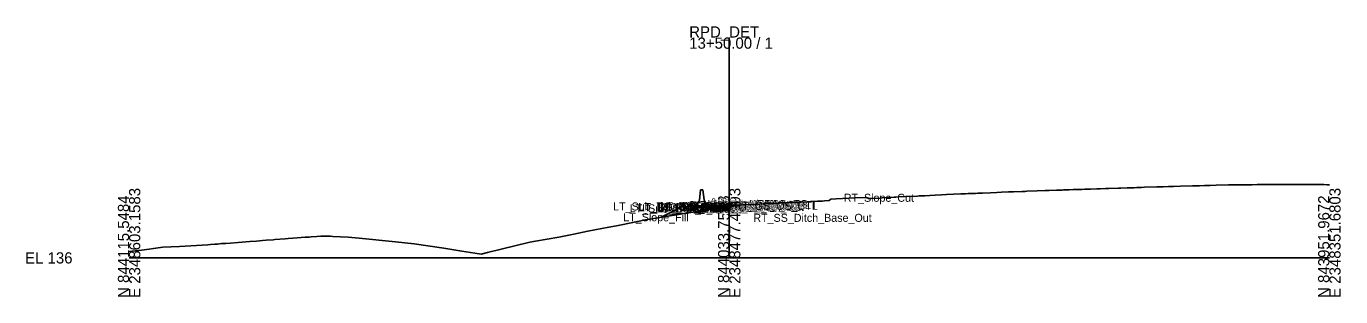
# Model space of a CAD drawing. Extents: x -26 to 2348503, y -10 to 844218.
# Drawn here: x -25.7 to 302.8, y 3490.3 to 3557.9 of the extents above; entities that cross this region are included whole.
import ezdxf

# ---------------------------------------------------------------- set-up
doc = ezdxf.new("R2010")
doc.units = 0
for name, color, linetype in [('Default', 7, 'Continuous'), ('Exist Cross Section Cell', 7, 'Continuous'), ('Exist XS Center Line Elevation Label', 7, 'Continuous'), ('Exist XS Ground Line', 7, 'Continuous'), ('Old_Level_1', 7, 'Continuous'), ('Prop CMT Pvmt Course 1', 7, 'Continuous'), ('Prop CMT Pvmt Course 1 Wedge', 7, 'Continuous'), ('Prop CMT Pvmt Course 2', 7, 'Continuous'), ('Prop CMT Pvmt Course 2 Wedge', 7, 'Continuous'), ('Prop CMT Pvmt Course 3', 7, 'Continuous'), ('Prop CMT Pvmt Course 3 Wedge', 7, 'Continuous'), ('Prop CMT Pvmt Surface', 7, 'Continuous'), ('Prop CMT Pvmt Surface Shoulder', 7, 'Continuous'), ('Prop CMT Pvmt Wedge Surface 1', 7, 'Continuous'), ('Prop CMT Pvmt Wedge Surface 2', 7, 'Continuous'), ('Prop CMT Pvmt Wedge Surface 3', 7, 'Continuous'), ('Prop CMT Shld Paved Course 1', 7, 'Continuous'), ('Prop CMT Shld Paved Course 2', 7, 'Continuous'), ('Prop CMT Shld Paved Course 3', 7, 'Continuous'), ('Prop CMT Slope Grass', 7, 'Continuous'), ('Prop CMT Subgrade Earthwork', 7, 'Continuous'), ('Prop XS Earthwork Shape', 7, 'Continuous'), ('Prop XS SE Text', 7, 'Continuous'), ('Typical Median Barrier CELL', 7, 'Continuous')]:
    doc.layers.add(name, color=color, linetype=linetype)

# ---------------------------------------------------------------- blocks, each defined once
blk = doc.blocks.new('TYPE T DOUBLE FACE BARRIER')
at = {"layer": 'Typical Median Barrier CELL'}
for p, q in [((-0.33, 3.83), (-0.6, 1.3)), ((0, 3.83), (-0.33, 3.83)), ((0, 3.83), (0.33, 3.83)), ((0.33, 3.83), (0.6, 1.3)), ((-0.75, 0.91), (-1.21, 0.25)), ((-1.21, -0.17), (-1.21, 0.25)), ((0, 0), (0, 0)), ((0.75, 0.91), (1.21, 0.25)), ((1.21, -0.17), (1.21, 0.25)), ((-1.21, -0.17), (1.21, -0.17))]:
    blk.add_line(p, q, dxfattribs=at)
for centre, start, end in [((-1.43, 1.38), 325.0039, 353.9447), ((1.43, 1.38), 186.0553, 214.9937)]:
    blk.add_arc(centre, 0.833, start, end, dxfattribs=at)

msp = doc.modelspace()

# ---------------------------------------------------------------- linework, layer by layer
at = {"layer": 'Exist Cross Section Cell'}
for p, q in [((150, 3500), (150, 3555.06)), ((0, 3500), (150, 3500)), ((150, 3500), (300, 3500))]:
    msp.add_line(p, q, dxfattribs=at)
at = {"layer": 'Exist XS Ground Line'}
msp.add_lwpolyline([(0, 3501.59), (3.14, 3501.96), (4.99, 3502.16), (6.14, 3502.32), (8.43, 3502.68), (12.64, 3502.87), (19.65, 3503.25), (20.33, 3503.31), (21.47, 3503.41), (21.78, 3503.43), (22.08, 3503.46), (23.09, 3503.56), (23.44, 3503.57), (24.16, 3503.61), (25.37, 3503.71), (27.26, 3503.86), (30.18, 3504.09), (31.84, 3504.22), (33.34, 3504.35), (34.29, 3504.44), (36.05, 3504.54), (36.4, 3504.57), (39.03, 3504.77), (39.79, 3504.84), (40.94, 3504.92), (42.05, 3505), (44, 3505.14), (44.97, 3505.21), (45.52, 3505.25), (46.95, 3505.35), (47.91, 3505.39), (48.81, 3505.41), (50.31, 3505.4), (50.91, 3505.37), (54.76, 3505.17), (57.47, 3504.96), (66.58, 3504.02), (71.26, 3503.52), (78.63, 3502.42), (83.21, 3501.71), (86.44, 3501.22), (88.04, 3500.96), (89.59, 3501.36), (100.17, 3503.96), (101.61, 3504.2), (107.4, 3505.19), (111.17, 3505.95), (114.63, 3506.66), (119.95, 3507.69), (121.85, 3508.05), (123.1, 3508.28), (129.08, 3509.54), (142.45, 3511.66), (145.9, 3512.25), (146.83, 3512.35), (150, 3512.78), (151.18, 3512.94), (152, 3513.06), (153.48, 3513.26), (155.66, 3513.37), (157.28, 3513.44), (158.7, 3513.5), (160.22, 3513.57), (160.9, 3513.6), (161.34, 3513.62), (163.68, 3513.74), (164.75, 3513.8), (167.33, 3513.91), (169.38, 3514.01), (169.94, 3514.04), (170.31, 3514.06), (172.05, 3514.15), (173.21, 3514.21), (173.83, 3514.25), (175.02, 3514.35), (175.41, 3514.68), (176.69, 3514.75), (181.47, 3514.99), (184.29, 3515.13), (184.8, 3514.8), (185.45, 3514.84), (187.69, 3514.94), (188.22, 3514.97), (189.83, 3515.07), (191.2, 3515.15), (191.64, 3515.18), (192.34, 3515.22), (194.18, 3515.31), (197.06, 3515.45), (197.44, 3515.48), (198.19, 3515.51), (198.86, 3515.53), (200.12, 3515.59), (201.5, 3515.66), (203.1, 3515.74), (204.29, 3515.81), (206.09, 3515.89), (207.9, 3515.97), (209.08, 3516.02), (209.71, 3516.06), (210.68, 3516.1), (211.55, 3516.13), (212.11, 3516.15), (213.34, 3516.19), (215.27, 3516.26), (216.93, 3516.34), (218.02, 3516.39), (219.81, 3516.47), (221.05, 3516.52), (223.24, 3516.59), (223.97, 3516.62), (224.39, 3516.64), (226.96, 3516.74), (229, 3516.81), (229.98, 3516.84), (231.84, 3516.91), (233.19, 3516.95), (233.56, 3516.97), (235.01, 3517.02), (235.95, 3517.05), (236.82, 3517.08), (238.17, 3517.13), (238.92, 3517.15), (240.32, 3517.2), (241.89, 3517.25), (242.22, 3517.26), (242.74, 3517.28), (244.03, 3517.31), (244.86, 3517.34), (247.27, 3517.42), (247.85, 3517.44), (249.45, 3517.47), (250.83, 3517.53), (251.23, 3517.54), (251.85, 3517.57), (253.04, 3517.62), (253.82, 3517.64), (256.84, 3517.73), (258.47, 3517.79), (259.79, 3517.83), (260.29, 3517.84), (261.06, 3517.86), (262.77, 3517.92), (265.76, 3518.01), (267.51, 3518.04), (268.76, 3518.09), (269.33, 3518.1), (270.21, 3518.12), (271.72, 3518.15), (274.8, 3518.22), (276.58, 3518.24), (277.72, 3518.26), (279.37, 3518.28), (280.67, 3518.29), (281.96, 3518.31), (283.96, 3518.34), (286.62, 3518.35), (288.55, 3518.35), (289.63, 3518.35), (291, 3518.33), (292.59, 3518.35), (293.11, 3518.35), (294.79, 3518.33), (295.58, 3518.33), (296.4, 3518.32), (297.72, 3518.31), (298.59, 3518.3), (299.48, 3518.28), (300, 3518.28)], dxfattribs=at)
at = {"layer": 'Prop CMT Pvmt Course 1'}
for p, q in [((150, 3513.15), (142, 3512.98)), ((142, 3512.98), (142, 3512.73)), ((142, 3512.73), (150, 3512.9)), ((150, 3513.15), (153.22, 3513.22)), ((150, 3512.9), (150, 3513.15)), ((150, 3512.9), (150, 3513.15)), ((152.11, 3513.07), (150, 3513.03)), ((150, 3512.9), (150, 3513.03)), ((150, 3513.03), (150, 3513.03)), ((150, 3513.03), (150, 3512.9)), ((150, 3513.03), (150, 3512.9)), ((150, 3512.9), (150, 3512.9)), ((150, 3512.9), (150, 3512.9))]:
    msp.add_line(p, q, dxfattribs=at)
at = {"layer": 'Prop CMT Pvmt Course 1 Wedge'}
msp.add_line((150, 3513.03), (152.11, 3513.07), dxfattribs=at)
at = {"layer": 'Prop CMT Pvmt Course 2'}
for p, q in [((142, 3512.73), (150, 3512.9)), ((150, 3512.9), (142, 3512.73)), ((142, 3512.73), (142, 3512.73)), ((150, 3512.9), (150, 3512.9))]:
    msp.add_line(p, q, dxfattribs=at)
at = {"layer": 'Prop CMT Pvmt Course 2 Wedge'}
msp.add_line((150, 3512.9), (151.05, 3512.93), dxfattribs=at)
at = {"layer": 'Prop CMT Pvmt Course 3'}
for p, q in [((150, 3512.9), (142, 3512.73)), ((142, 3512.73), (142, 3512.4)), ((142, 3512.4), (150, 3512.57)), ((150, 3512.57), (150, 3512.9))]:
    msp.add_line(p, q, dxfattribs=at)
at = {"layer": 'Prop CMT Pvmt Course 3 Wedge'}
msp.add_line((150, 3512.9), (151.05, 3512.93), dxfattribs=at)
at = {"layer": 'Prop CMT Pvmt Surface'}
for q in [(142, 3512.98), (153.22, 3513.22)]:
    msp.add_line((150, 3513.15), q, dxfattribs=at)
at = {"layer": 'Prop CMT Pvmt Surface Shoulder'}
msp.add_line((142, 3512.98), (142, 3512.98), dxfattribs=at)
at = {"layer": 'Prop CMT Pvmt Wedge Surface 1'}
msp.add_line((150, 3513.03), (152.11, 3513.07), dxfattribs=at)
at = {"layer": 'Prop CMT Pvmt Wedge Surface 2'}
msp.add_line((150, 3512.9), (151.05, 3512.93), dxfattribs=at)
at = {"layer": 'Prop CMT Pvmt Wedge Surface 3'}
msp.add_line((150, 3512.9), (151.05, 3512.93), dxfattribs=at)
at = {"layer": 'Prop CMT Shld Paved Course 1'}
for p, q in [((142, 3512.98), (141.74, 3512.73)), ((141.74, 3512.73), (142, 3512.73)), ((142, 3512.98), (142, 3512.98)), ((142, 3512.73), (142, 3512.98))]:
    msp.add_line(p, q, dxfattribs=at)
at = {"layer": 'Prop CMT Shld Paved Course 2'}
for p, q in [((142, 3512.73), (141.74, 3512.73)), ((141.74, 3512.73), (141.74, 3512.73)), ((141.74, 3512.73), (142, 3512.73)), ((142, 3512.73), (142, 3512.73))]:
    msp.add_line(p, q, dxfattribs=at)
at = {"layer": 'Prop CMT Shld Paved Course 3'}
for p, q in [((141.24, 3512.72), (140.9, 3512.38)), ((140.9, 3512.38), (142, 3512.4)), ((141.74, 3512.73), (141.24, 3512.72)), ((142, 3512.73), (141.74, 3512.73)), ((142, 3512.4), (142, 3512.73))]:
    msp.add_line(p, q, dxfattribs=at)
at = {"layer": 'Prop CMT Slope Grass'}
for p, q in [((138, 3512.66), (133, 3510.16)), ((142, 3512.98), (138, 3512.66))]:
    msp.add_line(p, q, dxfattribs=at)
at = {"layer": 'Prop CMT Subgrade Earthwork'}
for p, q in [((140.9, 3512.38), (140.43, 3512.85)), ((142, 3512.4), (140.9, 3512.38)), ((148.13, 3512.53), (142, 3512.4))]:
    msp.add_line(p, q, dxfattribs=at)
at = {"layer": 'Prop XS Earthwork Shape'}
msp.add_lwpolyline([(138, 3512.66), (133, 3510.16), (142.45, 3511.66), (145.9, 3512.25), (146.83, 3512.35), (148.13, 3512.53), (142, 3512.4), (140.9, 3512.38), (140.43, 3512.85)], close=True, dxfattribs=at)

# ---------------------------------------------------------------- block references
at = {"layer": 'Old_Level_1', "yscale": -0.9999999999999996, "rotation": -178.75751143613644}
msp.add_blockref('TYPE T DOUBLE FACE BARRIER', (143.2, 3513.17), dxfattribs=at)

# ---------------------------------------------------------------- texts
at = {"layer": 'Default'}
for s, height, p in [('RT_Slope_Cut', 2, (178.63, 3514.02)), ('LT_Sub_Trench_Out_DLT', 2, (120.99, 3511.85)), ('LT_Sub_Trench_Out', 2, (125.11, 3511.38)), ('LT_PS3_Shelf_Out', 2, (127.23, 3511.72)), ('LT_GS_OS_CTL', 2, (127.37, 3511.66)), ('LT_PS3_OEOP', 2, (131.98, 3511.73)), ('LT_PS2_OEOP', 2, (131.98, 3511.73)), ('LT_Sub_OEOT', 2, (132.08, 3511.4)), ('LT_PV3_OEOT', 2, (132.17, 3511.73)), ('LT_PV2_OEOT', 2, (132.17, 3511.73)), ('LT_PV1_OEOT', 2, (132.74, 3511.98)), ('LT_PS1_OEOP', 2, (132.8, 3511.98)), ('RT_PV_IEEOP_EG', 2, (138.14, 3511.78)), ('LT_Sub_OEEOP', 2, (139.21, 3511.57)), ('LT_PV2_OEEOP', 2, (139.31, 3511.9)), ('LT_PV3_OEEOP', 2, (139.31, 3511.9)), ('LT_PV1_OEEOP', 2, (139.87, 3512.03)), ('RT_PV2_IEEOP', 2, (139.91, 3511.9)), ('RT_PV3_IEEOP', 2, (139.91, 3511.9)), ('LT_PV2_IEEOP', 2, (139.95, 3511.9)), ('RT_Sub_Trench_Out_DLT', 2, (140.09, 3512.2)), ('RT_PV1_IEEOP', 2, (140.47, 3512.03)), ('LT_PV1_IEEOP', 2, (140.52, 3512.03)), ('RT_Sub_Trench_Out', 2, (143.25, 3511.72)), ('PV2_PGL', 2, (143.91, 3511.9)), ('PV1_PGL', 2, (144.47, 3512.15)), ('RT_Sub Tie Out', 2, (144.58, 3512.44)), ('RT_PS3_Shelf_Out', 2, (144.69, 3512.06)), ('RT_PV_OEEOP_EG', 2, (144.78, 3512.44)), ('RT_Sub_OEEOP', 2, (146.45, 3511.73)), ('RT_PV2_OEEOP', 2, (146.55, 3512.06)), ('RT_PV3_OEEOP', 2, (146.55, 3512.06)), ('RT_PV1_OEEOP', 2, (147.12, 3512.19)), ('RT_Sub_OEOT', 2, (148.03, 3511.74)), ('RT_PV3_OEOT', 2, (148.13, 3512.08)), ('RT_PV2_OEOT', 2, (148.13, 3512.08)), ('RT_PS3_OEOP', 2, (148.44, 3512.07)), ('RT_PS2_OEOP', 2, (148.44, 3512.07)), ('RT_PV1_OEOT', 2, (148.69, 3512.33)), ('RT_PS1_OEOP', 2, (148.76, 3512.33)), ('RT_GS_OS_CTL', 2, (151.32, 3512.01)), ('LT_Slope_Fill', 2, (123.52, 3509.16)), ('RT_SS_Ditch_Base_Out', 2, (156.03, 3509.01)), ('-', 0.0001, (0, 3500))]:
    msp.add_text(s, height=height, dxfattribs=at).set_placement(p)
at = {"layer": 'Exist Cross Section Cell'}
for s, p in [('13+50.00 / 1', (140, 3552.26)), ('RPD_DET', (140, 3555.06)), ('EL 136', (-26, 3498.6))]:
    msp.add_text(s, height=2.8, dxfattribs=at).set_placement(p)
for s, p in [('N 844115.5484', (0, 3490)), ('E 2348603.1583', (2.8, 3490)), ('N 844033.7578', (150, 3490)), ('E 2348477.4193', (152.8, 3490)), ('N 843951.9672', (300, 3490)), ('E 2348351.6803', (302.8, 3490))]:
    msp.add_text(s, height=2.8, rotation=90, dxfattribs=at).set_placement(p)
at = {"layer": 'Exist XS Center Line Elevation Label'}
msp.add_text('148.78', height=1.2, dxfattribs=at).set_placement((147.55, 3511.18))
at = {"layer": 'Prop XS SE Text'}
for s, rotation, p in [('2:1', 26.5651, (133.84, 3511.12)), ('0.022', 1.2425, (145.57, 3513.36))]:
    msp.add_text(s, height=1.5, rotation=rotation, dxfattribs=at).set_placement(p)

doc.saveas('drawing.dxf')
